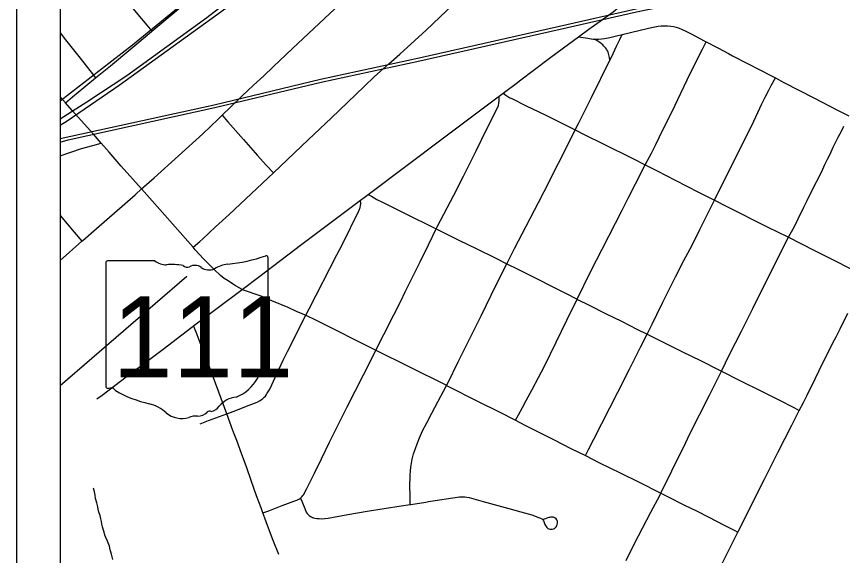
# Model space of a CAD drawing. Extents: x -483 to 680, y 0 to 440.
# Drawn here: x 436.4 to 503.5, y 318.8 to 362.6 of the extents above; entities that cross this region are included whole.
import ezdxf

# ---------------------------------------------------------------- set-up
doc = ezdxf.new("R2010")
doc.units = 0
for name, color, linetype in [('Default', 7, 'Continuous'), ('GM_X_City_Street', 7, 'Continuous'), ('GM_X_County_Road', 7, 'Continuous'), ('GM_X_Minor_River', 7, 'Continuous'), ('GM_X_Rail_Line', 7, 'Continuous'), ('GM_X_State_Route', 7, 'Continuous'), ('GM_X_State_Shield', 7, 'Continuous'), ('SH_Text', 7, 'Continuous')]:
    doc.layers.add(name, color=color, linetype=linetype)

msp = doc.modelspace()

# ---------------------------------------------------------------- linework, layer by layer
at = {"layer": 'Default'}
msp.add_lwpolyline([(436.426, 419.526), (436.426, 243.16), (629.121, 243.16), (629.121, 419.526)], close=True, dxfattribs=at)
at = {"layer": 'GM_X_City_Street'}
msp.add_line((440.398, 355.602), (439.962, 356.088), dxfattribs=at)
for points in [[(446.592, 348.609), (447.6, 349.505), (451.56, 353.096), (452.823, 354.292), (453.142, 354.598), (453.853, 355.28), (454.747, 356.143), (455.694, 357.039), (456.515, 357.813), (457.296, 358.538), (458.847, 360.034), (461.894, 362.875), (463.784, 364.673), (467.631, 368.263), (468.213, 368.813), (469.44, 369.97), (470.215, 370.685), (471.035, 371.435), (471.661, 372.029), (472.071, 372.402), (472.787, 373.078), (472.966, 373.247), (473.573, 373.819)], [(442.222, 367.71), (442.641, 367.213), (443.322, 366.406), (446.298, 362.798), (447.018, 361.939), (447.435, 361.44)], [(440.398, 355.602), (440.983, 356.101), (441.885, 356.869), (442.837, 357.643), (444.057, 358.633), (447.21, 361.25), (447.435, 361.44), (449.716, 363.363)], [(450.775, 343.87), (451.323, 344.352), (451.557, 344.559), (452.61, 345.529), (453.7, 346.548), (457.297, 349.918), (460.126, 352.605), (462.03, 354.392), (464.675, 356.93), (465.529, 357.744), (466.677, 358.789), (467.567, 359.564), (468.804, 360.693), (469.707, 361.526), (471.932, 363.639)], [(482.084, 360.967), (482.858, 360.857), (483.138, 360.817), (483.3, 360.802), (483.408, 360.798), (483.729, 360.8), (484.213, 360.855), (484.636, 360.934), (485.177, 361.055), (485.644, 361.168), (487.777, 361.689), (488.176, 361.774), (488.58, 361.835), (488.828, 361.864), (489.086, 361.872), (489.335, 361.87), (489.596, 361.846), (489.824, 361.808), (490.035, 361.752), (490.268, 361.674), (490.51, 361.579), (490.829, 361.428), (491.136, 361.279), (491.701, 360.983), (492.264, 360.688), (492.484, 360.573), (493.419, 360.084), (494.291, 359.616), (494.613, 359.445), (495.874, 358.781), (497.776, 357.8), (498.094, 357.636), (498.792, 357.276), (501.209, 356.006), (503.14, 355.016), (504.065, 354.554)], [(439.962, 361.296), (440.412, 360.742), (441.492, 359.378), (442.48, 358.103), (442.837, 357.643)], [(468.414, 322.964), (468.415, 323.469), (468.417, 323.737), (468.391, 324.418), (468.411, 325.273), (468.45, 325.747), (468.494, 326.147), (468.585, 326.64), (468.698, 327.072), (468.839, 327.508), (468.973, 327.881), (469.177, 328.388), (469.428, 328.95), (469.763, 329.609), (470.178, 330.392), (470.667, 331.315), (471.373, 332.648), (471.471, 332.833), (472.331, 334.57), (473.288, 336.505), (474.177, 338.301), (475.002, 339.969), (476.068, 342.123), (476.272, 342.535), (476.888, 343.78), (477.836, 345.596), (478.833, 347.514), (479.755, 349.29), (480.182, 350.127), (480.768, 351.273), (481.831, 353.405), (482.123, 353.99), (483.143, 356.05), (484.651, 359.071), (484.8, 359.388), (485.196, 360.222), (485.446, 360.75), (485.644, 361.168)], [(476.989, 329.807), (477.222, 330.245), (477.536, 330.835), (477.847, 331.42), (478.321, 332.313), (478.833, 333.278), (479.328, 334.212), (480.277, 336.158), (481.156, 337.958), (481.983, 339.654), (483.089, 341.92), (484.013, 343.705), (485.634, 346.884), (486.133, 347.852), (486.737, 349.027), (487.528, 350.563), (488.018, 351.515), (488.355, 352.169), (488.663, 352.792), (489.172, 353.839), (489.698, 354.921), (490.416, 356.398), (490.939, 357.476), (491.429, 358.482), (492.185, 359.982), (492.484, 360.573)], [(484.651, 359.071), (484.608, 359.305), (484.572, 359.502), (484.542, 359.621), (484.512, 359.727), (484.469, 359.82), (484.41, 359.92), (484.365, 359.989), (484.305, 360.069), (484.245, 360.148), (484.165, 360.231), (484.062, 360.327), (483.963, 360.414), (483.827, 360.522), (483.676, 360.629), (483.408, 360.798)], [(482.657, 326.934), (482.915, 327.436), (483.342, 328.266), (485.286, 332.092), (486.241, 333.975), (487.137, 335.746), (487.675, 336.806), (488.091, 337.628), (488.46, 338.409), (488.959, 339.407), (489.974, 341.462), (490.67, 342.784), (491.341, 344.044), (491.959, 345.324), (492.156, 345.704), (493.145, 347.701), (493.529, 348.478), (495.425, 352.247), (496.347, 354.135), (496.999, 355.534), (497.273, 356.086), (497.553, 356.633), (497.756, 357.01), (498.094, 357.636)], [(456.451, 322.271), (456.936, 322.455), (457.472, 322.66), (458.022, 322.87), (458.531, 323.064), (458.965, 323.229), (459.212, 323.324), (459.328, 323.377), (459.419, 323.423), (459.505, 323.476), (459.612, 323.576), (459.703, 323.687), (459.768, 323.786), (459.859, 323.951), (460.011, 324.251), (460.144, 324.526), (460.635, 325.517), (461.218, 326.683), (461.854, 328.028), (463.303, 330.91), (465.271, 334.781), (465.638, 335.511), (466.272, 336.775), (467.089, 338.377), (467.645, 339.483), (468.023, 340.259), (468.652, 341.537), (469.22, 342.691), (469.902, 344.077), (470.534, 345.361), (470.616, 345.527), (471.964, 348.114), (472.759, 349.659), (473.787, 351.71), (474.602, 353.385), (475.491, 355.155), (475.585, 355.395), (475.625, 355.578), (475.66, 355.774), (475.654, 356.023), (475.65, 356.161)], [(475.966, 356.396), (476.181, 356.243), (476.352, 356.128), (476.525, 356.029), (476.673, 355.953), (477.854, 355.378), (479.389, 354.63), (481.331, 353.66), (481.831, 353.405), (482.615, 353.004), (484.047, 352.297), (486.564, 351.048), (487.528, 350.563), (488.491, 350.078), (489.955, 349.324), (491.848, 348.355), (493.145, 347.701), (494.165, 347.187), (497.487, 345.514), (499.045, 344.748), (499.176, 344.681), (501.229, 343.64), (503.007, 342.736), (505.064, 341.685)], [(443.318, 352.341), (442.688, 353.058), (440.94, 354.998), (440.398, 355.602)], [(453.142, 354.598), (453.604, 354.074), (454.876, 352.635), (456.019, 351.325), (456.727, 350.545), (457.297, 349.918)], [(485.96, 318.405), (486.63, 319.737), (487.979, 322.327), (488.694, 323.705), (488.79, 323.896), (489.687, 325.706), (490.074, 326.476), (490.622, 327.591), (491.144, 328.694), (492.738, 331.844), (493.707, 333.81), (494.375, 335.164), (495.331, 337.058), (496.26, 338.9), (497.388, 341.136), (499.176, 344.681), (499.311, 344.949), (499.639, 345.573), (499.944, 346.196), (500.409, 347.137), (500.672, 347.686), (501.03, 348.401), (501.864, 350.042), (502.117, 350.592), (502.328, 351.025), (502.539, 351.437), (502.803, 351.997), (503.203, 352.811), (503.457, 353.318), (503.653, 353.708)], [(439.962, 351.299), (441.72, 351.895), (442.619, 352.146), (443.318, 352.341)], [(446.592, 348.609), (444.923, 350.476), (443.961, 351.611), (443.318, 352.341)], [(450.775, 343.87), (450.337, 344.381), (448.481, 346.479), (447.453, 347.644), (446.592, 348.609)], [(465.007, 348.167), (465.263, 348.022), (465.714, 347.766), (466.157, 347.536), (466.874, 347.174), (467.9, 346.676), (470.534, 345.361), (472.382, 344.459), (473.826, 343.743), (475.277, 343.042), (476.272, 342.535), (477.166, 342.08), (478.635, 341.355), (480.052, 340.63), (481.028, 340.132), (481.983, 339.654), (482.077, 339.606), (482.914, 339.201), (484.357, 338.474), (485.585, 337.852), (486.85, 337.222), (487.675, 336.806), (489.094, 336.092), (490.546, 335.367), (491.998, 334.66), (493.546, 333.892), (493.707, 333.81), (495.197, 333.055), (496.96, 332.175), (498.256, 331.519), (499.639, 330.812), (500.041, 330.606)], [(451.34, 329.52), (452.037, 329.784), (453.518, 330.323), (454.026, 330.521), (455.346, 331.037), (455.975, 331.29), (456.178, 331.389), (456.307, 331.472), (456.448, 331.571), (456.557, 331.675), (456.65, 331.774), (456.744, 331.899), (456.809, 332.006), (456.91, 332.169), (456.999, 332.339), (457.167, 332.696), (457.45, 333.296), (457.784, 334.002), (458.109, 334.693), (458.442, 335.397), (459.943, 338.339), (460.207, 338.856), (462.45, 343.251), (462.882, 344.075), (464.278, 346.876), (464.356, 347.102), (464.386, 347.258), (464.398, 347.391), (464.387, 347.701)], [(439.962, 346.463), (441.099, 345.109), (441.747, 344.356)], [(454.765, 340.449), (454.154, 340.781), (453.616, 341.13), (453.296, 341.337), (452.993, 341.573), (452.498, 342.053), (452.147, 342.404), (451.618, 342.929), (450.947, 343.669), (450.775, 343.87)], [(454.765, 340.449), (456.273, 339.914), (456.641, 339.765), (457.137, 339.557), (458.48, 338.996), (459.142, 338.689), (459.611, 338.484), (459.943, 338.339)], [(459.943, 338.339), (460.73, 337.97), (461.753, 337.468), (464.533, 336.061), (465.638, 335.511)], [(457.74, 318.89), (457.29, 320.045), (456.831, 321.267), (456.604, 321.861), (456.451, 322.271), (456.298, 322.678), (455.94, 323.653), (455.503, 324.906), (455.145, 325.935), (454.707, 327.116), (454.318, 328.165), (454.013, 328.988), (453.518, 330.323), (451.939, 334.584), (451.408, 335.976), (451.018, 336.97), (450.817, 337.48)], [(465.638, 335.511), (468.368, 334.152), (471.313, 332.679), (471.373, 332.648)], [(471.373, 332.648), (473.954, 331.34), (475.642, 330.491), (476.989, 329.807)], [(476.989, 329.807), (477.748, 329.421), (480.132, 328.218), (481.483, 327.525), (482.657, 326.934)], [(482.657, 326.934), (483.742, 326.388), (485.538, 325.502), (486.971, 324.795), (488.79, 323.896)], [(459.505, 323.476), (459.605, 323.235), (459.847, 322.636), (459.976, 322.351), (460.051, 322.237), (460.12, 322.15), (460.212, 322.058), (460.308, 321.992), (460.394, 321.947), (460.474, 321.912), (460.571, 321.879), (460.682, 321.851), (460.828, 321.827), (461.016, 321.812), (461.196, 321.805), (461.495, 321.827), (461.753, 321.853), (463.341, 322.142), (464.931, 322.414), (467.688, 322.845), (468.414, 322.964), (468.478, 322.975), (469.677, 323.162), (469.908, 323.207), (472.416, 323.577), (472.649, 323.594), (472.849, 323.59), (473.029, 323.566), (473.216, 323.538), (474.351, 323.217), (476.447, 322.635), (477.398, 322.358), (478.298, 322.111), (478.94, 321.89), (479.002, 321.86), (479.06, 321.833), (479.115, 321.795), (479.188, 321.725), (479.243, 321.652), (479.37, 321.324), (479.412, 321.244), (479.457, 321.162), (479.522, 321.086), (479.602, 321.022), (479.677, 320.986), (479.765, 320.959), (479.862, 320.944), (479.947, 320.947), (480.067, 320.977), (480.149, 321.024), (480.22, 321.085), (480.282, 321.157), (480.325, 321.227), (480.369, 321.334), (480.389, 321.445), (480.387, 321.507), (480.377, 321.6), (480.336, 321.715), (480.271, 321.808), (480.183, 321.878), (480.125, 321.906), (480.052, 321.928), (479.979, 321.942), (479.879, 321.942), (479.814, 321.932), (479.746, 321.914), (479.678, 321.893), (479.527, 321.845), (479.415, 321.803), (479.315, 321.762), (479.22, 321.72)], [(488.79, 323.896), (489.334, 323.621), (490.718, 322.92), (491.676, 322.437), (492.685, 321.924), (493.892, 321.31), (494.266, 321.115), (494.74, 320.878), (495.051, 320.723)]]:
    msp.add_lwpolyline(points, dxfattribs=at)
at = {"layer": 'GM_X_County_Road'}
msp.add_line((439.962, 342.787), (441.747, 344.356), dxfattribs=at)
msp.add_lwpolyline([(441.747, 344.356), (441.814, 344.415), (442.939, 345.394), (446.068, 348.143), (446.592, 348.609)], dxfattribs=at)
at = {"layer": 'GM_X_Minor_River'}
msp.add_line((439.962, 332.64), (450.257, 341.534), dxfattribs=at)
msp.add_lwpolyline([(444.248, 318.479), (444.145, 318.937), (444.04, 319.282), (443.972, 319.588), (443.829, 319.971), (443.685, 320.279), (443.614, 320.47), (443.544, 320.7), (443.474, 320.968), (443.403, 321.159), (443.37, 321.35), (443.338, 321.579), (443.267, 321.808), (443.236, 322.075), (443.129, 322.344), (443.059, 322.573), (443.026, 322.764), (442.958, 323.108), (442.853, 323.452), (442.821, 323.719), (442.752, 323.987), (442.684, 324.292)], dxfattribs=at)
at = {"layer": 'GM_X_Rail_Line'}
for points in [[(439.962, 353.805), (440.537, 354.159), (444.765, 357.038), (454.209, 363.877), (466.892, 374.314), (484.04, 388.767), (490.495, 394.933), (494.333, 399.412), (497.997, 403.426), (501.893, 411.221), (504.313, 415.991)], [(503.331, 415.991), (496.773, 403.832), (468.217, 379.408), (454.006, 366.991), (445.861, 360.303), (439.962, 355.754)], [(484.839, 389.99), (466.852, 374.583), (456.638, 366.198), (451.891, 362.52), (445.397, 357.813), (442.15, 355.676), (439.962, 354.274)], [(439.962, 352.709), (452.496, 355.464), (461.132, 357.533), (469.137, 359.265), (480.561, 361.858), (486.746, 363.266), (492.56, 364.475), (499.084, 365.533), (505.431, 366.062), (510.22, 366.315), (531.193, 365.736), (558.338, 364.831), (598.401, 363.549), (625.586, 362.679)], [(439.962, 352.418), (440.628, 352.601), (452.551, 355.222), (461.187, 357.291), (469.191, 359.023), (480.616, 361.615), (486.799, 363.023), (492.605, 364.23), (499.114, 365.286), (505.448, 365.814), (510.223, 366.066), (531.185, 365.487), (558.33, 364.583), (598.393, 363.3), (625.586, 362.431)]]:
    msp.add_lwpolyline(points, dxfattribs=at)
at = {"layer": 'GM_X_State_Route'}
for points in [[(483.12, 361.729), (483.849, 362.25), (484.905, 363.014), (485.386, 363.388), (485.443, 363.433), (487.062, 364.781), (488.143, 365.715), (489.787, 367.141), (491.43, 368.56), (491.617, 368.72), (491.799, 368.883), (492.403, 369.41), (493.016, 369.925), (493.672, 370.489), (494.606, 371.297), (495.032, 371.666), (496.955, 373.329), (498.231, 374.407), (498.456, 374.602)], [(477.151, 357.277), (477.309, 357.395), (479.738, 359.234), (480.887, 360.087), (482.084, 360.967), (483.039, 361.671), (483.12, 361.729)], [(454.765, 340.449), (456.188, 341.528), (459.513, 344.035), (464.387, 347.701), (464.679, 347.92), (465.007, 348.167), (471.139, 352.775), (473.174, 354.31), (475.464, 356.024), (475.65, 356.161), (475.966, 356.396), (477.151, 357.277)], [(446.489, 334.194), (448.445, 335.674), (449.039, 336.121), (450.667, 337.368), (450.817, 337.48), (454.765, 340.449)], [(491.202, 313.096), (491.393, 313.468), (491.658, 314.008), (491.945, 314.607), (492.55, 315.807), (493.523, 317.681), (494.696, 320.015), (495.051, 320.723), (495.226, 321.07), (495.841, 322.291), (497.205, 325.012), (498.292, 327.176), (499.433, 329.415), (500.041, 330.606), (500.374, 331.261), (500.677, 331.854), (501.322, 333.173), (501.651, 333.859), (502.042, 334.653), (502.52, 335.6), (502.77, 336.101), (503.034, 336.59), (503.364, 337.245), (503.993, 338.52)], [(442.948, 331.54), (443.382, 331.862), (445.919, 333.762), (446.489, 334.194)]]:
    msp.add_lwpolyline(points, dxfattribs=at)
at = {"layer": 'GM_X_State_Shield'}
for p, q in [((456.864, 337.78), (456.864, 343.014)), ((443.681, 342.594), (443.681, 332.588)), ((447.672, 342.766), (443.811, 342.766)), ((456.863, 337.781), (456.864, 337.78))]:
    msp.add_line(p, q, dxfattribs=at)
for centre, radius, start, end in [((452.168, 356.407), 13.981, 275.84447, 288.90645), ((456.718, 343.035), 0.147, 351.86209, 97.738), ((443.832, 342.615), 0.153, 98.1301, 188.1301), ((448.591, 343.927), 1.481, 231.61951, 271.11188), ((449.082, 337.148), 5.318, 80.48669, 94.98827), ((450.29, 342.667), 0.427, 219.79206, 297.10237), ((450.917, 341.51), 0.889, 54.46668, 119.14113), ((453.952, 339.71), 2.813, 97.34618, 120.76885), ((452.064, 343.097), 1.069, 233.85621, 294.82819), ((456.708, 337.759), 0.157, 289.60381, 7.73413), ((456.83, 337.395), 0.227, 107.94398, 210.33697), ((455.385, 336.734), 1.363, 340.03296, 23.64957), ((457.39, 335.589), 0.992, 136.8065, 186.92959), ((452.951, 334.923), 3.497, 292.30889, 8.98584), ((443.833, 332.566), 0.154, 171.95839, 258.30661), ((443.857, 333.589), 1.176, 267.33899, 280.60386), ((444.097, 332.01), 0.424, 29.74838, 93.27175), ((449.45, 341), 10.096, 240.41292, 257.1985), ((454.426, 329.778), 1.915, 94.40312, 142.57675), ((446.44, 328.092), 3.159, 47.18416, 75.83597), ((451.999, 331.618), 1.13, 282.87319, 323.27711), ((449.857, 331.961), 2.004, 230.70037, 286.29184), ((451.161, 331.211), 1.068, 268.77702, 315.54927), ((452.128, 330.242), 0.301, 65.75173, 132.64842), ((451.015, 328.501), 1.647, 85.69512, 111.20995)]:
    msp.add_arc(centre, radius, start, end, dxfattribs=at)
at = {"layer": 'SH_Text'}
msp.add_lwpolyline([(439.962, 246.695), (625.586, 246.695), (625.586, 415.991), (439.962, 415.991)], close=True, dxfattribs=at)
msp.add_lwpolyline([(439.962, 246.695), (625.586, 246.695), (625.586, 415.991), (439.962, 415.991)], close=True, dxfattribs=at)

# ---------------------------------------------------------------- texts
at = {"layer": 'GM_X_State_Shield'}
msp.add_text('111', height=6.5918, dxfattribs=at).set_placement((444.212, 333.293))

doc.saveas('drawing.dxf')
